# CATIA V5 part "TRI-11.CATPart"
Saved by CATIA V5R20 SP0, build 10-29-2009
Part number: _TRI-11
Definition: NONE
Nomenclature: _TRI-11
Source: Unknown
Description: PART-_TRI-11-DESC
Bounding box of the stored display mesh (mm): x 0 to 17.5, y -5.5 to 5.5, z -5.5 to 5.5
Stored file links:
  C:\Users\Utente\Desktop\IO LAVORO\3D X SITO CF\X SITO\PLASTICA\TRI\TRI-11.CATPart
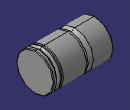
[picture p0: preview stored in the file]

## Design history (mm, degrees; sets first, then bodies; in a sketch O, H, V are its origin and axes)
Body1 "_TRI-11" (main body)
  Solid1: solid without history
